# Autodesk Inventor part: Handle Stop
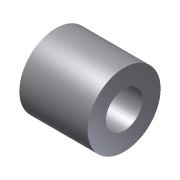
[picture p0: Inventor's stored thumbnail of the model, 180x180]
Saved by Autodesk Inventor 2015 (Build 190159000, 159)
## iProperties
Shininess: 77.0
Length Units: 11269
Angle Units: 11279
Time Units: 11290
Mass Units: 11283
Length Display Precision: 3
Angle Display Precision: 2
Compacted: True
Created: 2002-02
Part Number: Handle Stop
Document SubType Name: Modeling
Designer: ***
Density: 1 g/cm^3
Material: Generic
Appearance: Default
Density: 0.0
Volumn: 0.0
Area: 0.0
PropertySet Name: Model Information
Control State: 0
Master: False
Checked Out: False
Author: ***
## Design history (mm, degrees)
sketch "Sketch1"
  geometry: L1 (0, 0)-(0, -2); L2 (0, -2)-(8, -2); L3 (8, -2)-(8, 13); L4 (8, 13)-(4, 13); L5 (4, 13)-(4, 0); L6 (4, 0)-(0, 0)
  constraints: 12 end point, 4 parallel, 1 perpendicular, 1 vertical
  dimensions: "d0" = 16 diameter of L3 L1; "d1" = 8 diameter of L5 L1; "d2" = 2 distance of L1.start L1.end; "d3" = 15 distance of L2.end L3.end
revolve "Revolution1" sketch "Sketch1" stored, may be unused: angle "d4" = 90 deg
body "Solid1"
